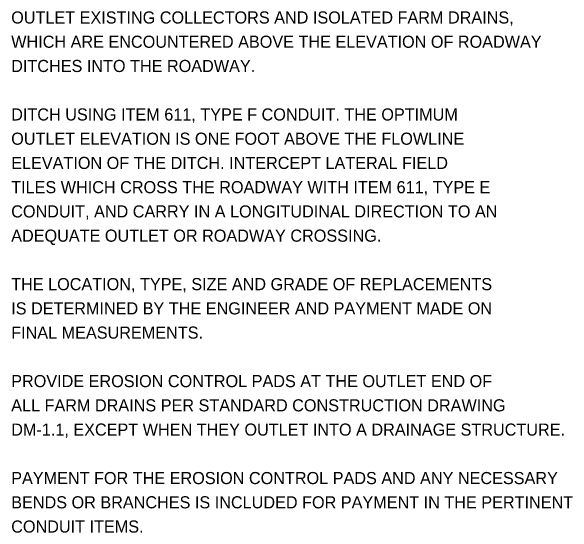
# Model space of a CAD drawing. Extents: x -8.9 to 68, y -11.9 to 22.
# Drawn here: x 27.42 to 33.91, y -11.88 to -5.86 of the extents above; entities that cross this region are included whole.
import ezdxf

# ---------------------------------------------------------------- set-up
doc = ezdxf.new("R2010")
doc.units = 0
doc.layers.add('SH_Text', color=7, linetype='Continuous')

msp = doc.modelspace()

# ---------------------------------------------------------------- texts
at = {"layer": 'SH_Text'}
for s, p in [('OUTLET EXISTING COLLECTORS AND ISOLATED FARM DRAINS,', (27.4198, -5.9973)), ('WHICH ARE ENCOUNTERED ABOVE THE ELEVATION OF ROADWAY', (27.4198, -6.2773)), ('DITCHES INTO THE ROADWAY.', (27.4198, -6.5573)), ('DITCH USING ITEM 611, TYPE F CONDUIT. THE OPTIMUM', (27.4198, -7.1173)), ('OUTLET ELEVATION IS ONE FOOT ABOVE THE FLOWLINE', (27.4198, -7.3973)), ('ELEVATION OF THE DITCH. INTERCEPT LATERAL FIELD', (27.4198, -7.6773)), ('TILES WHICH CROSS THE ROADWAY WITH ITEM 611, TYPE E', (27.4198, -7.9573)), ('CONDUIT, AND CARRY IN A LONGITUDINAL DIRECTION TO AN', (27.4198, -8.2373)), ('ADEQUATE OUTLET OR ROADWAY CROSSING.', (27.4198, -8.5173)), ('THE LOCATION, TYPE, SIZE AND GRADE OF REPLACEMENTS', (27.4198, -9.0773)), ('IS DETERMINED BY THE ENGINEER AND PAYMENT MADE ON', (27.4198, -9.3573)), ('FINAL MEASUREMENTS.', (27.4198, -9.6373)), ('PROVIDE EROSION CONTROL PADS AT THE OUTLET END OF', (27.4198, -10.1973)), ('ALL FARM DRAINS PER STANDARD CONSTRUCTION DRAWING', (27.4198, -10.4773)), ('DM-1.1, EXCEPT WHEN THEY OUTLET INTO A DRAINAGE STRUCTURE.', (27.4198, -10.7573)), ('PAYMENT FOR THE EROSION CONTROL PADS AND ANY NECESSARY', (27.4198, -11.3173)), ('BENDS OR BRANCHES IS INCLUDED FOR PAYMENT IN THE PERTINENT', (27.4198, -11.5973)), ('CONDUIT ITEMS.', (27.4198, -11.8773))]:
    msp.add_text(s, height=0.14, dxfattribs=at).set_placement(p)

doc.saveas('drawing.dxf')
